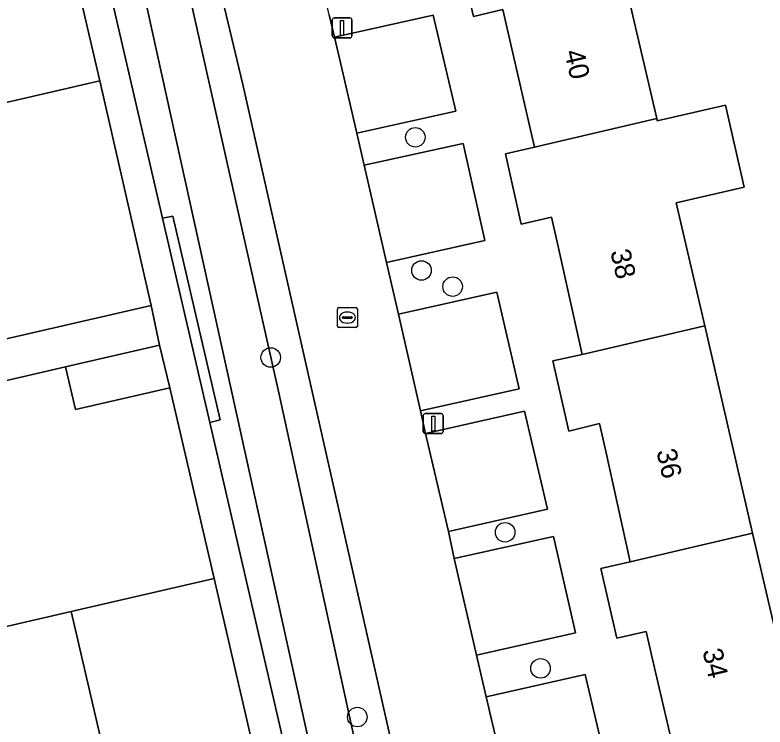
# Model space of a CAD drawing. Extents: x 156412 to 157779, y 382335 to 383768.
# Drawn here: x 156911.01 to 156948.58, y 382866.54 to 382902.2 of the extents above; entities that cross this region are included whole.
import ezdxf

# ---------------------------------------------------------------- set-up
doc = ezdxf.new("R2010")
doc.units = 0
for name, color, linetype in [('IMGEO_Berm_groen', 7, 'Continuous'), ('IMGEO_Boom', 7, 'Continuous'), ('IMGEO_Erf', 7, 'Continuous'), ('IMGEO_Greppel_droge_sloot', 7, 'Continuous'), ('IMGEO_Groenvoorziening', 7, 'Continuous'), ('IMGEO_Haag', 7, 'Continuous'), ('IMGEO_Lichtmast', 7, 'Continuous'), ('IMGEO_Muur', 7, 'Continuous'), ('IMGEO_Pand', 7, 'Continuous'), ('IMGEO_Pand_nummerreeks', 7, 'Continuous'), ('IMGEO_Parkeervlak_open', 7, 'Continuous'), ('IMGEO_Rijbaan_lokaal_gesloten', 7, 'Continuous'), ('IMGEO_Rioolput', 7, 'Continuous'), ('IMGEO_Voetpad_open', 7, 'Continuous')]:
    doc.layers.add(name, color=color, linetype=linetype)

msp = doc.modelspace()

# ---------------------------------------------------------------- linework, layer by layer
at = {"layer": 'IMGEO_Berm_groen'}
for points in [[(156918.446, 382912.971), (156917.996, 382913.122), (156913.092, 382914.594), (156913.71, 382912.282), (156918.396, 382892.022), (156918.921, 382892.119), (156921.287, 382881.92), (156920.762, 382881.795), (156925.852, 382859.789), (156930.181, 382860.808)], [(156922.418, 382898.725), (156919.179, 382912.277)], [(156930.667, 382860.901), (156929.898, 382865.604), (156922.418, 382898.725)]]:
    msp.add_lwpolyline(points, dxfattribs=at)
msp.add_lwpolyline([(156928.493, 382863.788), (156926.278, 382863.313), (156915.815, 382910.793), (156917.946, 382911.213), (156924.219, 382883.281)], close=True, dxfattribs=at)
at = {"layer": 'IMGEO_Boom'}
for centre in [(156931.065, 382896.074), (156931.374, 382889.406), (156932.935, 382888.596), (156923.822, 382885.047), (156935.563, 382876.296), (156937.338, 382869.48), (156928.159, 382867.044)]:
    msp.add_circle(centre, 0.489, dxfattribs=at)
at = {"layer": 'IMGEO_Erf'}
for points in [[(156935.969, 382928.126), (156938.368, 382917.746), (156940.758, 382907.406), (156940.785, 382907.289), (156944.196, 382908.075), (156945.146, 382903.963), (156941.735, 382903.177), (156943.161, 382897.01), (156943.188, 382896.893), (156946.598, 382897.679), (156947.546, 382893.577), (156944.136, 382892.791), (156945.561, 382886.624), (156947.96, 382876.242), (156949.418, 382869.934)], [(156906.812, 382870.703), (156913.825, 382872.323), (156920.983, 382873.977), (156918.763, 382883.533), (156914.039, 382882.442), (156913.547, 382884.574), (156908.775, 382883.472)]]:
    msp.add_lwpolyline(points, dxfattribs=at)
msp.add_lwpolyline([(156915.255, 382898.9), (156906.295, 382896.833), (156907.108, 382893.323), (156898.239, 382891.277), (156897.771, 382893.297), (156892.783, 382892.146), (156892.439, 382893.637), (156888.737, 382892.783), (156885.006, 382891.922), (156885.35, 382890.431), (156880.343, 382889.276), (156879.97, 382890.76), (156871.201, 382888.741), (156862.433, 382886.721), (156853.655, 382884.699), (156844.666, 382882.629), (156847.325, 382871.335), (156903.057, 382884.256), (156902.503, 382886.644), (156905.282, 382887.29), (156905.837, 382884.902), (156917.831, 382887.65)], close=True, dxfattribs=at)
at = {"layer": 'IMGEO_Greppel_droge_sloot'}
msp.add_lwpolyline([(156917.946, 382911.213), (156915.815, 382910.793), (156926.278, 382863.313), (156928.493, 382863.788), (156924.219, 382883.281)], close=True, dxfattribs=at)
at = {"layer": 'IMGEO_Groenvoorziening'}
msp.add_lwpolyline([(156918.396, 382892.022), (156920.762, 382881.795), (156921.287, 382881.92), (156918.921, 382892.119)], close=True, dxfattribs=at)
at = {"layer": 'IMGEO_Haag'}
msp.add_lwpolyline([(156918.396, 382892.022), (156920.762, 382881.795), (156921.287, 382881.92), (156918.921, 382892.119)], close=True, dxfattribs=at)
at = {"layer": 'IMGEO_Lichtmast'}
for p, q in [((156926.9, 382901.151), (156926.9, 382901.951)), ((156926.9, 382901.951), (156926.9, 382901.151)), ((156927, 382902.051), (156927.79, 382902.051)), ((156927.79, 382902.051), (156927, 382902.051)), ((156927.89, 382901.951), (156927.89, 382901.151)), ((156927.89, 382901.151), (156927.89, 382901.951)), ((156927.79, 382901.051), (156927, 382901.051)), ((156927, 382901.051), (156927.79, 382901.051)), ((156931.464, 382881.338), (156931.464, 382882.138)), ((156931.464, 382882.138), (156931.464, 382881.338)), ((156931.564, 382882.238), (156932.354, 382882.238)), ((156932.354, 382882.238), (156931.564, 382882.238)), ((156932.454, 382882.138), (156932.454, 382881.338)), ((156932.454, 382881.338), (156932.454, 382882.138)), ((156932.354, 382881.238), (156931.564, 382881.238)), ((156931.564, 382881.238), (156932.354, 382881.238))]:
    msp.add_line(p, q, dxfattribs=at)
for points in [[(156927.32, 382901.926), (156927.47, 382901.926), (156927.47, 382901.176), (156927.32, 382901.176), (156927.32, 382901.926)], [(156931.884, 382882.113), (156932.034, 382882.113), (156932.034, 382881.363), (156931.884, 382881.363), (156931.884, 382882.113)]]:
    msp.add_lwpolyline(points, dxfattribs=at)
for centre, start, end in [((156927, 382901.951), 90, 180), ((156927, 382901.951), 90, 180), ((156927.79, 382901.951), 0, 90), ((156927.79, 382901.951), 360, 90), ((156927, 382901.151), 180, 270), ((156927, 382901.151), 180, 270), ((156927.79, 382901.151), 270, 0), ((156927.79, 382901.151), 270, 0), ((156931.564, 382882.138), 90, 180), ((156931.564, 382882.138), 90, 180), ((156932.354, 382882.138), 0, 90), ((156932.354, 382882.138), 360, 90), ((156931.564, 382881.338), 180, 270), ((156931.564, 382881.338), 180, 270), ((156932.354, 382881.338), 270, 0), ((156932.354, 382881.338), 270, 0)]:
    msp.add_arc(centre, 0.1, start, end, dxfattribs=at)
at = {"layer": 'IMGEO_Muur'}
for points in [[(156915.255, 382898.9), (156917.831, 382887.65)], [(156918.763, 382883.533), (156920.983, 382873.977)]]:
    msp.add_lwpolyline(points, dxfattribs=at)
at = {"layer": 'IMGEO_Pand'}
for points in [[(156903.931, 382907.05), (156906.295, 382896.833), (156915.255, 382898.9), (156912.205, 382912.006), (156908.806, 382911.227), (156909.005, 382910.37), (156906.53, 382909.797), (156907.001, 382907.761)], [(156934.621, 382905.958), (156933.16, 382905.629), (156933.98, 382902.125), (156935.442, 382902.467), (156935.745, 382901.152), (156937.027, 382895.58), (156943.161, 382897.01), (156941.735, 382903.177), (156945.146, 382903.963), (156944.196, 382908.075), (156940.785, 382907.289), (156940.758, 382907.406)], [(156939.416, 382885.204), (156945.561, 382886.624), (156944.136, 382892.791), (156947.546, 382893.577), (156946.598, 382897.679), (156943.188, 382896.893), (156943.161, 382897.01), (156937.027, 382895.58), (156935.574, 382895.24), (156936.373, 382891.731), (156937.895, 382892.078), (156938.186, 382890.76)], [(156939.416, 382885.204), (156937.961, 382884.872), (156938.761, 382881.351), (156940.295, 382881.739), (156940.586, 382880.42), (156941.821, 382874.823), (156947.96, 382876.242), (156945.561, 382886.624)], [(156913.547, 382884.574), (156914.039, 382882.442), (156918.763, 382883.533), (156918.253, 382885.661)], [(156957.277, 382866.967), (156956.23, 382871.503), (156949.418, 382869.934), (156947.96, 382876.242), (156941.821, 382874.823), (156940.359, 382874.483), (156941.154, 382870.986), (156942.634, 382871.323), (156942.937, 382870.007), (156944.325, 382863.994)], [(156913.825, 382872.323), (156916.198, 382862.134), (156917.925, 382862.535), (156918.273, 382861.034), (156923.698, 382862.279), (156920.983, 382873.977)], [(156913.825, 382872.323), (156906.812, 382870.703), (156909.525, 382859.004), (156914.785, 382860.225), (156914.437, 382861.725), (156916.198, 382862.134)]]:
    msp.add_lwpolyline(points, close=True, dxfattribs=at)
at = {"layer": 'IMGEO_Parkeervlak_open'}
for points in [[(156928.138, 382896.285), (156933.089, 382897.377), (156931.963, 382902.188), (156927.014, 382901.089), (156927.28, 382899.952)], [(156934.544, 382890.908), (156933.468, 382895.769), (156928.505, 382894.672), (156929.616, 382889.799)], [(156936.273, 382883.479), (156935.149, 382888.319), (156930.22, 382887.222), (156931.32, 382882.368)], [(156937.684, 382877.452), (156936.53, 382882.359), (156931.57, 382881.247), (156932.721, 382876.333)], [(156939.093, 382871.265), (156937.986, 382876.091), (156933.016, 382874.979), (156934.136, 382870.145)], [(156940.702, 382864.343), (156939.581, 382869.179), (156934.622, 382868.06), (156935.752, 382863.214)]]:
    msp.add_lwpolyline(points, close=True, dxfattribs=at)
at = {"layer": 'IMGEO_Rijbaan_lokaal_gesloten'}
for points in [[(156935.752, 382863.214), (156934.622, 382868.06), (156934.136, 382870.145), (156933.016, 382874.979), (156932.721, 382876.333), (156931.57, 382881.247), (156931.32, 382882.368), (156930.22, 382887.222), (156929.616, 382889.799), (156928.505, 382894.672), (156928.138, 382896.285), (156927.28, 382899.952), (156927.014, 382901.089), (156926.746, 382902.205), (156926.191, 382904.624), (156925.261, 382908.509), (156923.616, 382915.861), (156921.59, 382924.592)], [(156919.179, 382912.277), (156922.418, 382898.725), (156929.898, 382865.604), (156930.667, 382860.901)]]:
    msp.add_lwpolyline(points, dxfattribs=at)
at = {"layer": 'IMGEO_Rioolput'}
for p, q in [((156927.159, 382886.619), (156927.159, 382887.471)), ((156927.234, 382887.545), (156928.086, 382887.545)), ((156927.647, 382887.325), (156927.672, 382887.325)), ((156928.16, 382887.471), (156928.16, 382886.619)), ((156927.418, 382887.039), (156927.418, 382887.051)), ((156927.856, 382887.002), (156927.458, 382887.002)), ((156927.461, 382887.088), (156927.859, 382887.088)), ((156927.902, 382887.051), (156927.902, 382887.039)), ((156928.086, 382886.545), (156927.234, 382886.545)), ((156927.67, 382886.765), (156927.645, 382886.765))]:
    msp.add_line(p, q, dxfattribs=at)
for points in [[(156927.159, 382886.619), (156927.159, 382887.471)], [(156927.234, 382887.545), (156928.086, 382887.545)], [(156928.16, 382887.471), (156928.16, 382886.619)], [(156928.086, 382886.545), (156927.234, 382886.545)]]:
    msp.add_lwpolyline(points, dxfattribs=at)
for centre, radius, start, end in [((156927.236, 382887.469), 0.0765, 91.552, 178.448), ((156927.236, 382887.469), 0.0765, 91.552, 178.448), ((156928.084, 382887.469), 0.0765, 1.552, 88.448), ((156928.084, 382887.469), 0.0765, 1.552, 88.448), ((156927.458, 382887.048), 0.0403, 85.8775, 175.7526), ((156927.455, 382887.038), 0.0366, 178.938, 274.7102), ((156927.859, 382887.045), 0.043, 264.8664, 352.4533), ((156927.863, 382887.05), 0.0386, 1.7309, 96.639), ((156927.236, 382886.621), 0.0765, 181.552, 268.448), ((156927.236, 382886.621), 0.0765, 181.552, 268.448), ((156928.084, 382886.621), 0.0765, 271.552, 358.448), ((156928.084, 382886.621), 0.0765, 271.552, 358.448)]:
    msp.add_arc(centre, radius, start, end, dxfattribs=at)
for centre, major_axis, ratio, start_param, end_param in [((156927.646, 382887.045), (-0.387, 0.002), 0.722429, 4.712389, 7.853982), ((156927.671, 382887.045), (-0.39, 0.002), 0.717154, 1.570796, 4.712389)]:
    msp.add_ellipse(centre, major_axis=major_axis, ratio=ratio, start_param=start_param, end_param=end_param, dxfattribs=at)
at = {"layer": 'IMGEO_Voetpad_open'}
for points in [[(156913.71, 382912.282), (156913.092, 382914.594), (156911.966, 382919.466), (156915.609, 382923.621), (156915.25, 382925.291), (156911.631, 382921.128), (156904.698, 382950.847), (156903.296, 382950.523), (156903.73, 382948.528), (156906.351, 382937.287), (156909.964, 382921.799), (156910.196, 382920.789), (156910.514, 382919.415), (156910.626, 382918.883), (156911.516, 382914.937), (156912.205, 382912.006), (156915.255, 382898.9), (156917.831, 382887.65), (156918.253, 382885.661), (156918.763, 382883.533), (156920.983, 382873.977), (156923.698, 382862.279)], [(156928.499, 382858.363), (156930.281, 382858.756), (156930.325, 382859.272), (156930.326, 382859.696), (156930.273, 382860.291), (156930.181, 382860.808), (156925.852, 382859.789), (156920.762, 382881.795), (156918.396, 382892.022), (156913.71, 382912.282)], [(156942.937, 382870.007), (156942.634, 382871.323), (156941.154, 382870.986), (156940.359, 382874.483), (156941.821, 382874.823), (156940.586, 382880.42), (156940.295, 382881.739), (156938.761, 382881.351), (156937.961, 382884.872), (156939.416, 382885.204), (156938.186, 382890.76), (156937.895, 382892.078), (156936.373, 382891.731), (156935.574, 382895.24), (156937.027, 382895.58), (156935.745, 382901.152), (156935.442, 382902.467), (156933.98, 382902.125), (156933.16, 382905.629)], [(156926.746, 382902.205), (156927.014, 382901.089), (156931.963, 382902.188), (156933.089, 382897.377), (156928.138, 382896.285), (156928.505, 382894.672), (156933.468, 382895.769), (156934.544, 382890.908), (156929.616, 382889.799), (156930.22, 382887.222), (156935.149, 382888.319), (156936.273, 382883.479), (156931.32, 382882.368), (156931.57, 382881.247), (156936.53, 382882.359), (156937.684, 382877.452), (156932.721, 382876.333), (156933.016, 382874.979), (156937.986, 382876.091), (156939.093, 382871.265), (156934.136, 382870.145), (156934.622, 382868.06), (156939.581, 382869.179), (156940.702, 382864.343)], [(156941.829, 382859.538), (156942.376, 382857.01), (156944.29, 382857.344), (156943.175, 382862.185), (156944.66, 382862.523), (156944.325, 382863.994), (156942.937, 382870.007)]]:
    msp.add_lwpolyline(points, dxfattribs=at)
msp.add_lwpolyline([(156885.399, 382878.073), (156889.962, 382879.127), (156894.749, 382880.232), (156899.445, 382881.317), (156903.986, 382882.366), (156908.775, 382883.472), (156913.547, 382884.574), (156918.253, 382885.661), (156917.831, 382887.65), (156905.837, 382884.902), (156903.057, 382884.256), (156847.325, 382871.335), (156847.84, 382869.397), (156852.577, 382870.491), (156857.35, 382871.594), (156862.024, 382872.674), (156866.68, 382873.749), (156871.355, 382874.829), (156875.927, 382875.885), (156880.705, 382876.988)], close=True, dxfattribs=at)

# ---------------------------------------------------------------- texts
at = {"layer": 'IMGEO_Pand_nummerreeks'}
for s, p in [('40', (156938.522, 382900.351)), ('38', (156940.828, 382890.354)), ('36', (156943.135, 382880.359)), ('34', (156945.442, 382870.362))]:
    msp.add_text(s, height=1, rotation=282.9936, dxfattribs=at).set_placement(p)

doc.saveas('drawing.dxf')
